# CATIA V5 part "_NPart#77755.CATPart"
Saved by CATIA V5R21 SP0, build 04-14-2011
Part number: Carcaça
Definition: Carcaça
Nomenclature: Carcaça
Source: Unknown
Bounding box of the stored display mesh (mm): x -5.973 to 6.027, y -13.5 to 0.9, z -4.992 to 5.008
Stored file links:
  C:\Users\beatr\OneDrive\Documents\UNB\2026_1\Pi1\Componentes eletronicos\_NPart#77755.CATPart
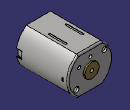
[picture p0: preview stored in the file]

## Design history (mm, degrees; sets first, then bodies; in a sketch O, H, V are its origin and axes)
Body1 "Sólido1" (main body)
  Solid1: solid without history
